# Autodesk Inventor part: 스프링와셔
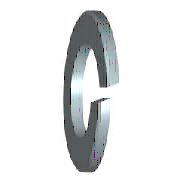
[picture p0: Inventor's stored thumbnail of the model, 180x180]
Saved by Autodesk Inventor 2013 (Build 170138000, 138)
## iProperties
Created: 2012-02
Part Number: 스프링와셔
Material: 강철, 연강
Description: 스프링 와셔
Document SubType Name: Modeling
Standard: JIS B 1251
Designer: mduedu
Standards Organization: JIS
Language: ko-KR
Size Designation: 번호 2 4
Categories: <MemberInstance><Categories><Category DisplayName="조임쇠" InternalName="e4da775c-781d-43d5-af7c-5136215cf5a6" Mnemonic="FSTN"><Category DisplayName="와셔" InternalN
Density: 7.86 g/cm^3
Mass: 0.247272 g
Surface Area: 1.02615 cm^2
Volume: 0.0314596 cm^3
IsCustomPart: 1
Author: mduedu
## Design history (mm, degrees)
sketch "스케치1"
  geometry: C1 r 3.8 at (0, 0); C2 r 2.05 at (0, 0); 1 further point
  constraints: 2 centre point, 2 coincident
  dimensions: "d0" = 4.1 diameter of C2 (= SD1); "d1" = 7.6 diameter of C1 (= SD2)
extrude "본체" new body sketch "스케치1" distance "d2" = 1 (= SD); taper "d3" = 0 deg
sketch "스케치2"
  geometry: L1 (0, -2.05)-(0, 2.05) reference; L2 (1, 3.8)-(1, -3.8) reference; L3 (-1.2, 0)-(7.2, 0) reference; L4 (0, -0.2)-(1, 0.164); L5 (0, 0.2)-(1, 0.564)
  constraints: 4 end point, 4 point on line, 1 parallel
  dimensions: "d4" = 0.2 distance from line of L3 L4.start (= 0.2 x SD); "d5" = 0.2 distance from line of L3 L5.start (= 0.2 x SD); "d6" = 70 deg angle of L2 L4 (= FAWI)
extrude "절단부" cut sketch "스케치2" stored distance "d7" = 1 (= SD); taper "d8" = 0 deg
workaxis "Work Axis1"
workplane "Work Plane1"
body "Solid1"
other parameters: "SD1" = 4.1 [user parameter; used in 1 equation term], "SD2" = 7.6 [user parameter; used in 1 equation term], "SD" = 1 [user parameter; used in 4 equation terms], "FAWI" = 70 deg [user parameter; used in 1 equation term], "d9" = 0, "d10" = 0, "d11" = 0, "d12" = 0, "SDI" = 1.4 [user parameter], "NND" = 4 [user parameter]
